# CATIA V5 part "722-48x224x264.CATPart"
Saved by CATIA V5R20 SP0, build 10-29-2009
Part number: 722-48x224x264
Definition: NONE
Nomenclature: 722-48x224x264
Source: Unknown
Description: 722-48x224x264
Bounding box of the stored display mesh (mm): x -24 to 24, y -23.825 to 23.825, z -206 to 58
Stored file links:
  C:\Users\Utente\Desktop\IO LAVORO\3D X SITO CF\X SITO\722\722-48x224x264.CATPart
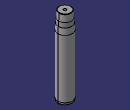
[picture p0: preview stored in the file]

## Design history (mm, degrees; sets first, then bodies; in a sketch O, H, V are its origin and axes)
Body1 "722-48x224x264" (main body)
  Solid1: solid without history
